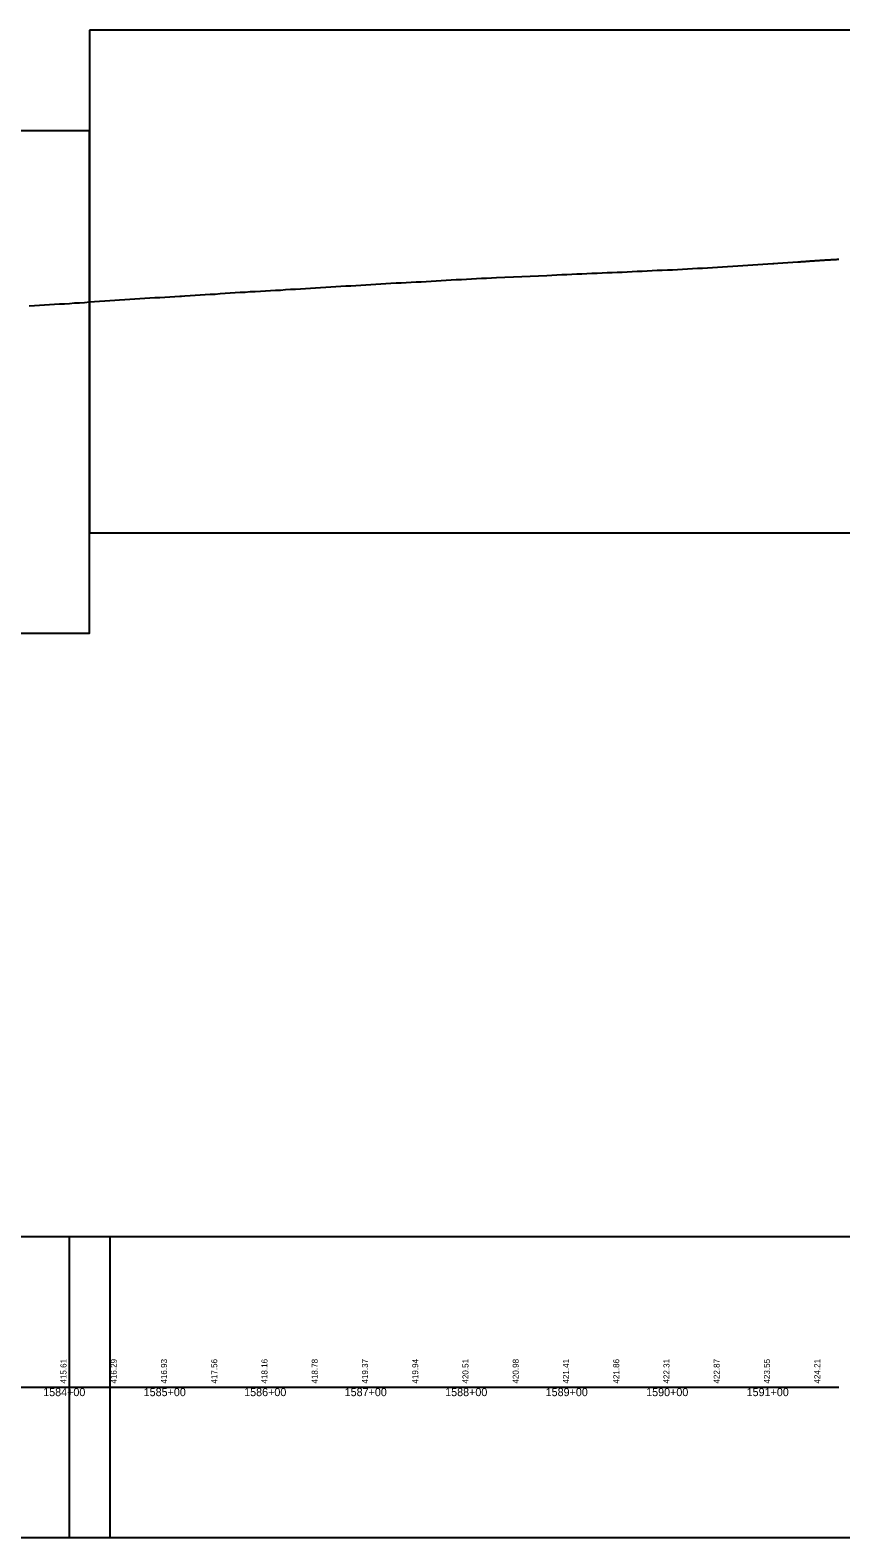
# Model space of a CAD drawing. Extents: x 2898 to 49495, y -15038 to -13538.
# Drawn here: x 47916 to 48723, y -15038 to -13538 of the extents above; entities that cross this region are included whole.
import ezdxf

# ---------------------------------------------------------------- set-up
doc = ezdxf.new("R2010")
doc.units = 0
for name, color, linetype in [('RD_DDB_Profile_EX', 7, 'Continuous'), ('RD_DDB_StaTX', 7, 'Continuous'), ('RD_DDB_StripGrade', 7, 'Continuous'), ('RD_GPK_Profile_Cell', 7, 'Continuous'), ('RD_SHT_ShtClip', 7, 'Continuous')]:
    doc.layers.add(name, color=color, linetype=linetype)

msp = doc.modelspace()

# ---------------------------------------------------------------- linework, layer by layer
at = {"layer": 'RD_DDB_Profile_EX'}
for points in [[(48650.3, -13770.9), (48655.3, -13770.6), (48656.1, -13770.6), (48660.3, -13770.3), (48665.3, -13769.9), (48670.3, -13769.6), (48675.3, -13769.2), (48680.3, -13768.9), (48681.3, -13768.8), (48682.3, -13768.8), (48683.3, -13768.7), (48684.3, -13768.6), (48685.3, -13768.5), (48686.3, -13768.5), (48687.3, -13768.5), (48688.3, -13768.3), (48689.3, -13768.3), (48690.3, -13768.2), (48691.3, -13768.2), (48692.3, -13768.1), (48693.3, -13768.1), (48694.3, -13768), (48695.3, -13767.9), (48696.3, -13767.9), (48697.3, -13767.8), (48698.3, -13767.7), (48699.3, -13767.6), (48700.3, -13767.5), (48701.3, -13767.5), (48702.3, -13767.4), (48703.3, -13767.4), (48704.3, -13767.3), (48705.3, -13767.2), (48706.3, -13767.2), (48707.3, -13767.1), (48708.3, -13767.1), (48709.3, -13767), (48710.3, -13767), (48711.3, -13766.9), (48712.3, -13766.9), (48713.3, -13766.8), (48714.3, -13766.7), (48715.3, -13766.7), (48716.3, -13766.6), (48717.3, -13766.5), (48718.3, -13766.5), (48719.3, -13766.4), (48720.3, -13766.3), (48721.1, -13766.2)], [(48115.3, -13799.8), (48120.3, -13799.6), (48125.3, -13799.2), (48130.3, -13799), (48135.3, -13798.6), (48140.3, -13798.4), (48145.3, -13798.1), (48150.3, -13797.8), (48155.3, -13797.5), (48160.3, -13797.3), (48165.3, -13797), (48170.3, -13796.6), (48175.3, -13796.3), (48180.3, -13796), (48185.3, -13795.7), (48190.3, -13795.4), (48195.3, -13795), (48200.3, -13794.7), (48205.3, -13794.5), (48210.3, -13794.1), (48215.3, -13793.9), (48220.3, -13793.6), (48225.3, -13793.2), (48230.3, -13793), (48231.6, -13792.9), (48235.3, -13792.7), (48240.3, -13792.5), (48245.3, -13792.1), (48250.3, -13791.8), (48255.3, -13791.5), (48260.3, -13791.1), (48265.3, -13790.7), (48270.3, -13790.5), (48275.3, -13790.2), (48280.3, -13790), (48285.3, -13789.7), (48290.3, -13789.6), (48295.3, -13789.2), (48300.3, -13788.9), (48305.3, -13788.7), (48310.3, -13788.4), (48315.3, -13788.1), (48320.3, -13787.9), (48325.3, -13787.6), (48330.3, -13787.3), (48335.3, -13786.9), (48340.3, -13786.7), (48345.3, -13786.5), (48350.3, -13786.1), (48355.3, -13785.8), (48360.3, -13785.5), (48365.3, -13785.2), (48370.3, -13785.1), (48375.3, -13784.8), (48380.4, -13784.5), (48405.4, -13783.5), (48430.3, -13782.4), (48435.3, -13782.1), (48440.3, -13781.9), (48445.3, -13781.7), (48450.3, -13781.6), (48455.3, -13781.3), (48460.3, -13781), (48465.3, -13780.8), (48470.3, -13780.6), (48475.3, -13780.4), (48480.3, -13780.2), (48485.3, -13779.9), (48490.3, -13779.7), (48495.3, -13779.5), (48500.3, -13779.3), (48505.3, -13779.1), (48510.3, -13778.9), (48515.3, -13778.7), (48520.3, -13778.4), (48525.3, -13778.1), (48530.3, -13777.9), (48535.3, -13777.6), (48540.3, -13777.4), (48545.3, -13777.3), (48550.3, -13777), (48555.3, -13776.8), (48560.3, -13776.6), (48565.3, -13776.3), (48570.3, -13776), (48575.3, -13775.7), (48580.3, -13775.4), (48585.3, -13775.1), (48590.3, -13774.8), (48595.3, -13774.6), (48600.3, -13774.3), (48605.3, -13774), (48610.3, -13773.7), (48615.3, -13773.4), (48620.3, -13773.1), (48625.3, -13772.7), (48630.3, -13772.4), (48635.3, -13772), (48640.3, -13771.7), (48645.3, -13771.3), (48650.3, -13770.9)], [(47915.4, -13812.7), (47920.4, -13812.5), (47925.4, -13812.1), (47930.4, -13811.7), (47935.4, -13811.4), (47940.4, -13811.1), (47945.4, -13810.8), (47950.4, -13810.6), (47955.3, -13810.3), (47960.4, -13809.9), (47965.4, -13809.6), (47970.4, -13809.3), (47975.4, -13808.9), (47980.4, -13808.5), (47985.4, -13808.1), (47990.4, -13807.8), (47995.4, -13807.5), (48000.4, -13807.1), (48005.3, -13806.9), (48010.3, -13806.5), (48015.3, -13806.2), (48020.3, -13805.8), (48025.3, -13805.5), (48030.3, -13805.2), (48035.3, -13804.9), (48040.3, -13804.5), (48042.9, -13804.4), (48045.3, -13804.3), (48050.3, -13804), (48055.3, -13803.7), (48060.3, -13803.4), (48065.3, -13803.2), (48066.7, -13803), (48070.3, -13802.7), (48075.3, -13802.4), (48080.3, -13802.1), (48085.3, -13801.8), (48090.3, -13801.5), (48095.3, -13801.2), (48100.3, -13801), (48105.3, -13800.5), (48110.3, -13800.2), (48115.3, -13799.8)]]:
    msp.add_lwpolyline(points, dxfattribs=at)
at = {"layer": 'RD_GPK_Profile_Cell'}
msp.add_line((2976.1, -14888.5), (48721.1, -14888.5), dxfattribs=at)
at = {"layer": 'RD_SHT_ShtClip'}
for points in [[(47975.4, -13538.5), (47975.4, -14038.5), (49475.4, -14038.5), (49475.4, -14038.5), (49475.4, -13538.5), (49475.4, -13538.5)], [(46475.4, -13638.5), (46475.4, -14138.5), (47975.4, -14138.5), (47975.4, -14138.5), (47975.4, -13638.5), (47975.4, -13638.5)], [(46455.4, -14738.5), (47995.4, -14738.5), (47995.4, -15038.5), (46455.4, -15038.5)], [(47955.4, -14738.5), (49495.4, -14738.5), (49495.4, -15038.5), (47955.4, -15038.5)]]:
    msp.add_lwpolyline(points, close=True, dxfattribs=at)

# ---------------------------------------------------------------- texts
at = {"layer": 'RD_DDB_StaTX'}
for s, p in [('1584+00', (47929.2, -14897.5)), ('1585+00', (48029.2, -14897.5)), ('1586+00', (48129.2, -14897.5)), ('1587+00', (48229.2, -14897.5)), ('1588+00', (48329.2, -14897.5)), ('1589+00', (48429.2, -14897.5)), ('1590+00', (48529.2, -14897.5)), ('1591+00', (48629.2, -14897.5))]:
    msp.add_text(s, height=8, dxfattribs=at).set_placement(p)
at = {"layer": 'RD_DDB_StripGrade'}
for s, p in [('415.61', (47952.4, -14885)), ('416.29', (48002.4, -14885)), ('416.93', (48052.4, -14885)), ('417.56', (48102.4, -14885)), ('418.16', (48152.4, -14885)), ('418.78', (48202.4, -14885)), ('419.37', (48252.4, -14885)), ('419.94', (48302.4, -14885)), ('420.51', (48352.4, -14885)), ('420.98', (48402.4, -14885)), ('421.41', (48452.4, -14885)), ('421.86', (48502.4, -14885)), ('422.31', (48552.4, -14885)), ('422.87', (48602.4, -14885)), ('423.55', (48652.4, -14885)), ('424.21', (48702.4, -14885))]:
    msp.add_text(s, height=6, rotation=90, dxfattribs=at).set_placement(p)

doc.saveas('drawing.dxf')
